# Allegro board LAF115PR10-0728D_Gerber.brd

Outline 228.4 x 155.5 mm; copper layers: TOP, GND1, IN1, VCC, IN2, IN3, GND2, BOTTOM. Coordinates in mm from the lower left corner of the outline.

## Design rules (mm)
net group 12: nets PCIE_RCOMPN PCIE_RCOMPP
net group CPU_DP3_AUX: nets CPU_DP3_AUXN CPU_DP3_AUXP
net group DDR-RESET: nets DDR4_DRAMRST# H_DRAMRST#
net group DIFFPAIR12: nets ICSP_CLK ICSP_DAT
net group DIFFPAIR15: nets NCT7718_DXN NCT7718_DXP
net group DIFFPAIR21: nets EDP_TX1 EDP_TX1#
net group DIFFPAIR22: nets USB_CAMERA_EDP USB_CAMERA_EDP#
net group DIFFPAIR24: nets USB3_CTX_DRX_N3 USB3_CTX_DRX_P3
net group DIFFPAIR25: nets USB3_CRX_DTX_N3 USB3_CRX_DTX_P3
net group DIFFPAIR27: nets PCIE_CTX_C_LANRX_N5 PCIE_CTX_C_LANRX_P5
net group GPU-XTAL_15/18_28/26: nets XTALIN XTALOUT
net group LAN_MDI2N: nets LAN_MDI2N LAN_MDI2P
net group LAN_MDI3N: nets LAN_MDI3N LAN_MDI3P
net group MDO2: nets MDO2+ MDO2-
net group MDO3: nets MDO3+ MDO3-
net group PECI: nets H_PECI PECI_EC
net group SW_USB_PN1: nets SW_USB_PN1 SW_USB_PP1
net group TYPEC_DP_N0: nets TYPEC_DP_N0 TYPEC_DP_P0
net group TYPEC_DP_N1: nets TYPEC_DP_N1 TYPEC_DP_P1
net group TYPEC_DP_N2: nets TYPEC_DP_N2 TYPEC_DP_P2
net group TYPEC_DP_N3: nets TYPEC_DP_N3 TYPEC_DP_P3
net group USB3_CRX_DTX_N3_C: nets USB3_CRX_DTX_N3_C USB3_CRX_DTX_P3_C
net group USB3_CTX_DRX_N3_C: nets USB3_CTX_DRX_N3_C USB3_CTX_DRX_P3_C
net group USB3_CTX_DRX_N3_R: nets USB3_CTX_DRX_N3_R USB3_CTX_DRX_P3_R
net group VGA_DP2_N0: nets VGA_DP2_N0 VGA_DP2_P0
net group VGA_DP2_N1: nets VGA_DP2_N1 VGA_DP2_P1
net group VGA_DP_AUXN: nets VGA_DP_AUXN VGA_DP_AUXP
net group 15: nets AUD_SPK_L+_C AUD_SPK_L-_C CLK_TP_SIO
net group AUDIO: nets AUD_HP1_JACK_L AUD_HP1_JACK_L1 AUD_HP1_JACK_R AUD_HP1_JACK_R1 CBN CBP CPVEE HPOUT_L HPOUT_R LINE1-L_C LINE1-L_R LINE1_L LINE1_R RING2 RING2_R SLEEVE SLEEVE_R
net group AUDIO-SPK: nets AUD_SPK_L+ AUD_SPK_L- AUD_SPK_R+ AUD_SPK_R+_C AUD_SPK_R- AUD_SPK_R-_C
net group CLK: nets CLK_PCIE_LAN_REQ# CLK_PCIE_NVME_REQ# CLK_PCIE_PEG_REQ# CLK_PCIE_WLAN_REQ# CLK_PCIE_WLAN_REQ#_R MEC_XTAL1 MEC_XTAL1_R MEC_XTAL2 PEG_CLKREQ# SUSCLK SUSCLK_EC SUSCLK_WLAN
net group CLK-24M: nets KBLR_XTAL_IN KBLR_XTAL_IN_R KBLR_XTAL_OUT KBLR_XTAL_OUT_R LANXIN LANXIN_R LANXOUT LANXOUT_R XCLK_BIASREF XTAL24_IN XTAL24_IN_R XTAL24_OUT
net group CPU: nets H_CATERR# H_PROCHOT# H_PROCHOT#_R H_THERMTRIP# H_VCCST_PWRGD VCCST_PWRGD XDP_OBS0_R XDP_OBS1_R XDP_OBS2_R XDP_OBS3_R
net group DDR-COMP: nets SM_RCOMP0 SM_RCOMP1 SM_RCOMP2
net group DIFFPAIR4: nets PCH_SMBDATA
net group DIFFPAIR23: nets DAT_TP_SIO
net group EDP: nets EDP_AUX EDP_AUX# EDP_AUX_DN EDP_AUX_DP EDP_TX0 EDP_TX0# EDP_TX0_DN EDP_TX0_DP EDP_TX1_DN EDP_TX1_DP
net group EDP-COMP: nets EDP_COMP
net group EMMC: nets EMMC_CLK EMMC_CLK_R EMMC_CMD EMMC_CMD_R EMMC_D0_R EMMC_D1_R EMMC_D2_R EMMC_D3_R EMMC_D4_R EMMC_D5_R EMMC_D6_R EMMC_D7_R EMMC_DATA0 EMMC_DATA1 EMMC_DATA2 EMMC_DATA3 EMMC_DATA4 EMMC_DATA5 EMMC_DATA6 EMMC_DATA7 EMMC_RCLK_R EMMC_RST# EMMC_RST#_R
net group ESPI: nets ESPI_CS# ESPI_RESET# PCH_ESPI_CLK PCH_ESPI_IO0 PCH_ESPI_IO1 PCH_ESPI_IO2 PCH_ESPI_IO3
net group HDA: nets DMIC_CLK DMIC_CLK_EDP DMIC_DATA DMIC_DATA_EDP HDA_BIT_CLK HDA_CODEC_BITCLK HDA_CODEC_RST# HDA_CODEC_SDIN0 HDA_CODEC_SDOUT HDA_CODEC_SYNC HDA_RST# HDA_SDIN0 HDA_SDOUT HDA_SYNC
net group HDMI: nets HDMI_CLK HDMI_CLK# HDMI_CLK#_R HDMI_CLK#_R_C HDMI_CLK_R HDMI_CLK_R_C HDMI_DATA0 HDMI_DATA0# HDMI_DATA0#_R HDMI_DATA0#_R_C HDMI_DATA0_R HDMI_DATA0_R_C HDMI_DATA1 HDMI_DATA1# HDMI_DATA1#_R HDMI_DATA1#_R_C HDMI_DATA1_R HDMI_DATA1_R_C HDMI_DATA2 HDMI_DATA2# HDMI_DATA2#_R HDMI_DATA2#_R_C HDMI_DATA2_R HDMI_DATA2_R_C
net group HDMI-DDC: nets CPU_DP1_CTRL_CLK CPU_DP1_CTRL_DATA DDC_CLK_HDMI DDC_DATA_HDMI
net group I2C: nets I2C0_SCL_TCH_PAD I2C0_SDA_TCH_PAD I2C_SCL_TP I2C_SDA_TP
net group KB: nets KSI0 KSI1 KSI2 KSI3 KSI4 KSI5 KSI6 KSI7 KSO0 KSO1 KSO2 KSO3 KSO4 KSO5 KSO6 KSO7 KSO8 KSO9 KSO10 KSO11 KSO12 KSO13 KSO14 KSO15
net group LAN: nets LAN_MDI0N LAN_MDI0P LAN_MDI1N LAN_MDI1P MDO0+ MDO0- MDO1+ MDO1-
net group PCIE: nets PCIE_CRX_C_LANTX_N5 PCIE_CRX_C_LANTX_P5 PCIE_CRX_LANTX_N5 PCIE_CRX_LANTX_P5 PCIE_CRX_WLANTX_N6 PCIE_CRX_WLANTX_P6 PCIE_CTX_C_WLANRX_N6 PCIE_CTX_C_WLANRX_P6 PCIE_CTX_LANRX_N5 PCIE_CTX_LANRX_P5 PCIE_CTX_WLANRX_N6 PCIE_CTX_WLANRX_P6
net group PCIE-GPU: nets PEG_GTX_C_HRX_N0 PEG_GTX_C_HRX_N1 PEG_GTX_C_HRX_N2 PEG_GTX_C_HRX_N3 PEG_GTX_C_HRX_P0 PEG_GTX_C_HRX_P1 PEG_GTX_C_HRX_P2 PEG_GTX_C_HRX_P3 PEG_GTX_HRX_N0 PEG_GTX_HRX_N1 PEG_GTX_HRX_N2 PEG_GTX_HRX_N3 PEG_GTX_HRX_P0 PEG_GTX_HRX_P1 PEG_GTX_HRX_P2 PEG_GTX_HRX_P3 PEG_HTX_C_GRX_N0 PEG_HTX_C_GRX_N1 PEG_HTX_C_GRX_N2 PEG_HTX_C_GRX_N3 PEG_HTX_C_GRX_P0 PEG_HTX_C_GRX_P1 PEG_HTX_C_GRX_P2 PEG_HTX_C_GRX_P3 PEG_HTX_GRX_N0 PEG_HTX_GRX_N1 PEG_HTX_GRX_N2 PEG_HTX_GRX_N3 PEG_HTX_GRX_P0 PEG_HTX_GRX_P1 PEG_HTX_GRX_P2 PEG_HTX_GRX_P3
net group PCIE-NVME: nets PCIE_CRX_NVMETX_N9 PCIE_CRX_NVMETX_N10 PCIE_CRX_NVMETX_N11 PCIE_CRX_NVMETX_N12 PCIE_CRX_NVMETX_P9 PCIE_CRX_NVMETX_P10 PCIE_CRX_NVMETX_P11 PCIE_CRX_NVMETX_P12 PCIE_CTX_C_NVMERX_N9 PCIE_CTX_C_NVMERX_N10 PCIE_CTX_C_NVMERX_N11 PCIE_CTX_C_NVMERX_N12 PCIE_CTX_C_NVMERX_P9 PCIE_CTX_C_NVMERX_P10 PCIE_CTX_C_NVMERX_P11 PCIE_CTX_C_NVMERX_P12 PCIE_CTX_NVMERX_N9 PCIE_CTX_NVMERX_N10 PCIE_CTX_NVMERX_N11 PCIE_CTX_NVMERX_N12 PCIE_CTX_NVMERX_P9 PCIE_CTX_NVMERX_P10 PCIE_CTX_NVMERX_P11 PCIE_CTX_NVMERX_P12
net group PLATFORM-CLK: nets CLK_ITPXDP_N CLK_ITPXDP_P CLK_PCIE_LAN_N2 CLK_PCIE_LAN_P2 CLK_PCIE_NVME_N4 CLK_PCIE_NVME_P4 CLK_PCIE_WLAN_N1 CLK_PCIE_WLAN_P1 CLK_PEG_VGA CLK_PEG_VGA#
net group RTC: nets PCH_RTCRST# PCH_RTCX1 PCH_RTCX2 SRTCRST#
net group SATA: nets SATA3_CRX_C_HDDTX_N0 SATA3_CRX_C_HDDTX_P0 SATA3_CRX_HDDTX_N0 SATA3_CRX_HDDTX_P0 SATA3_CTX_C_HDDRX_N0 SATA3_CTX_C_HDDRX_P0 SATA3_CTX_HDDRX_N0 SATA3_CTX_HDDRX_P0 SATA_CRX_C_ODDTX_N1 SATA_CRX_C_ODDTX_P1 SATA_CRX_ODDTX_N1 SATA_CRX_ODDTX_P1 SATA_CTX_C_ODDRX_N1 SATA_CTX_C_ODDRX_P1 SATA_CTX_ODDRX_N1 SATA_CTX_ODDRX_P1
net group SMBUS: nets CLK_SMB DAT_SMB MEM_SMBCLK MEM_SMBDATA MUX_I2C_CLK MUX_I2C_DATA PBAT_CHG_SMBCLK PBAT_CHG_SMBDAT PCH_SMBCLK SML0_SMBCLK SML0_SMBDATA SML1_SMBCLK SML1_SMBDATA THM_SML1_CLK THM_SML1_DATA TYPEC_SMBCLK TYPEC_SMBCLK_R TYPEC_SMBDA TYPEC_SMBDA_R VGA_SMB_CK3 VGA_SMB_DA3
net group SPI: nets PCH_SPI_CLK PCH_SPI_CLK_R PCH_SPI_CLK_TPM PCH_SPI_CS#0 PCH_SPI_CS#2 PCH_SPI_D0 PCH_SPI_D0_R PCH_SPI_D0_TPM PCH_SPI_D1 PCH_SPI_D1_R PCH_SPI_D1_TPM PCH_SPI_D2 PCH_SPI_D2_R PCH_SPI_D3 PCH_SPI_D3_R
net group SVID: nets H_CPU_SVIDALRT# VIDALERT_N VIDSCLK VIDSOUT
net group TYPEC-DP: nets CPU_DP2_AUXN CPU_DP2_AUXN_C CPU_DP2_AUXP CPU_DP2_AUXP_C CPU_DP2_N0 CPU_DP2_N0_C CPU_DP2_N1 CPU_DP2_N1_C CPU_DP2_N2 CPU_DP2_N2_C CPU_DP2_N3 CPU_DP2_N3_C CPU_DP2_P0 CPU_DP2_P0_C CPU_DP2_P1 CPU_DP2_P1_C CPU_DP2_P2 CPU_DP2_P2_C CPU_DP2_P3 CPU_DP2_P3_C DP_AUXN DP_AUXP DP_N0 DP_N1 DP_N2 DP_N3 DP_P0 DP_P1 DP_P2 DP_P3 TYPEC_DP_AUXN TYPEC_DP_AUXN_C TYPEC_DP_AUXP TYPEC_DP_AUXP_C TYPEC_DP_N0_C TYPEC_DP_N1_C TYPEC_DP_N2_C TYPEC_DP_N3_C TYPEC_DP_P0_C TYPEC_DP_P1_C TYPEC_DP_P2_C TYPEC_DP_P3_C TYPEC_RX2N TYPEC_RX2P TYPEC_TX2N TYPEC_TX2N_C TYPEC_TX2P TYPEC_TX2P_C
net group TYPEC-USB30: nets TYPEC_RX1N TYPEC_RX1P TYPEC_TX1N TYPEC_TX1N_C TYPEC_TX1P TYPEC_TX1P_C USB3_CRX_C_DTX_N4 USB3_CRX_C_DTX_P4 USB3_CRX_DTX_N4 USB3_CRX_DTX_P4 USB3_CTX_C_DRX_N4 USB3_CTX_C_DRX_P4 USB3_CTX_DRX_N4 USB3_CTX_DRX_P4
net group USB20: nets BOT_MUX_N BOT_MUX_N_R BOT_MUX_P BOT_MUX_P_R TOP_MUX_N TOP_MUX_N_R TOP_MUX_P TOP_MUX_P_R USB_PN1 USB_PN1_R USB_PN2 USB_PN2_R USB_PN3 USB_PN3_R USB_PN4 USB_PN4_R USB_PN5 USB_PN6 USB_PN6_R USB_PN7 USB_PN8 USB_PN8_TPNL USB_PN9 USB_PN10 USB_PP1 USB_PP1_R USB_PP2 USB_PP2_R USB_PP3 USB_PP3_R USB_PP4 USB_PP4_R USB_PP5 USB_PP6 USB_PP6_R USB_PP7 USB_PP8 USB_PP8_TPNL USB_PP9 USB_PP10
net group USB30: nets USB3_CRX_DTX_N1 USB3_CRX_DTX_N1_C USB3_CRX_DTX_N2 USB3_CRX_DTX_P1 USB3_CRX_DTX_P1_C USB3_CRX_DTX_P2 USB3_CTX_DRX_N1 USB3_CTX_DRX_N1_C USB3_CTX_DRX_N1_R USB3_CTX_DRX_N2 USB3_CTX_DRX_P1 USB3_CTX_DRX_P1_C USB3_CTX_DRX_P1_R USB3_CTX_DRX_P2
net group USB-COMP: nets USBCOMP
net group VRAM-ADD0: nets M0_MA0 M0_MA1 M0_MA2 M0_MA3 M0_MA4 M0_MA5 M0_MA6 M0_MA7 M0_MA8
net group VRAM-ADD1: nets M1_MA0 M1_MA1 M1_MA2 M1_MA3 M1_MA4 M1_MA5 M1_MA6 M1_MA7 M1_MA8
net group VRAM-CLK: nets M_CLK0 M_CLK1 M_CLK#0 M_CLK#1
net group VRAM-CTL0: nets M_CAS#0 M_CKE0 M_CS0B#0 M_RAS#0 M_WE#0
net group VRAM-CTL1: nets M_CAS#1 M_CKE1 M_CS1B#0 M_RAS#1 M_WE#1
net group VRAM-D0: nets M_DA0 M_DA1 M_DA2 M_DA3 M_DA4 M_DA5 M_DA6 M_DA7
net group VRAM-D1: nets M_DA8 M_DA9 M_DA10 M_DA11 M_DA12 M_DA13 M_DA14 M_DA15
net group VRAM-D2: nets M_DA16 M_DA17 M_DA18 M_DA19 M_DA20 M_DA21 M_DA22 M_DA23
net group VRAM-D3: nets M_DA24 M_DA25 M_DA26 M_DA27 M_DA28 M_DA29 M_DA30 M_DA31
net group VRAM-D4: nets M_DA32 M_DA33 M_DA34 M_DA35 M_DA36 M_DA37 M_DA38 M_DA39
net group VRAM-D5: nets M_DA40 M_DA41 M_DA42 M_DA43 M_DA44 M_DA45 M_DA46 M_DA47
net group VRAM-D6: nets M_DA48 M_DA49 M_DA50 M_DA51 M_DA52 M_DA53 M_DA54 M_DA55
net group VRAM-D7: nets M_DA56 M_DA57 M_DA58 M_DA59 M_DA60 M_DA61 M_DA62 M_DA63
net group VRAM-DBI: nets M_ADBI0 M_ADBI1 M_DBI0# M_DBI1# M_DBI2# M_DBI3# M_DBI4# M_DBI5# M_DBI6# M_DBI7#
net group VRAM-EDC: nets M_EDC_0 M_EDC_1 M_EDC_2 M_EDC_3 M_EDC_4 M_EDC_5 M_EDC_6 M_EDC_7
net group VRAM-WCK: nets M_WCKA0_0 M_WCKA0_0# M_WCKA0_1 M_WCKA0_1# M_WCKA1_0 M_WCKA1_0# M_WCKA1_1 M_WCKA1_1#
net group XDP: nets CFG0 CFG1 CFG2 CFG3 CFG4 CFG5 CFG6 CFG7 CFG8 CFG9 CFG10 CFG11 CFG12 CFG13 CFG14 CFG15 CFG16 CFG17 CFG18 CFG19 CPU_XDP_TCK0 PCH_JTAG_TCK1 PCH_RSMRST#_Q SOC_XDP_TDI SOC_XDP_TDO SOC_XDP_TMS SOC_XDP_TRST# XDP_HOOK0 XDP_ITP_PMODE XDP_PRDY# XDP_PREQ# XDP_PRSENT_CPU XDP_SPI_IO2 XDP_SPI_SI
nets with their own width: min track width 0.152; nets VCCSENSE VSSSENSE
nets with their own width: min track width 0.254; nets +1.0V_APLL +1.0V_VCCST +1.0V_VCCST_C +3.3V_ALW_DSW +3.3V_SPI +3VALW_PCH +3VLP +DP_VDDR +LAN_VDD33 +MPLL_PVDD +RTC_CELL +RTC_VCC +SPLL_PVDD +SPLL_VDDC +TPAN_VDD +TSVDD +VDD_CT +VDDR3 AC_B2B_S2_A AC_B2B_S2_B AC_B2B_S2_SW CFG_RCOMP HDMI_PLL_GND KB_BL_CTRL# KB_LED_DET_C LM393_P MCT0 MCT1 MCT2 MCT3 N17389450 N22328320 N22328488 N24193884 N24265247 N40598619
nets with their own width: min track width 0.305; nets +5V_KB_BL CPU_POPIRCOMP VDD10
nets with their own width: min track width 0.381; nets +1.8V_AVDD +1.8V_CPVDD +3V_DVDD +5V_AVDD +17.4V_BATT+ +FB0_VREFCL +FB0_VREFDL +FB1_VREFCL +FB1_VREFDL +MVREFDA +MVREFSA
nets with their own width: min track width 0.508; nets +1.0V_AMPHYPLL +1.0V_APLLEBB +1.0V_MPHYGT +1.0V_PRIM +1.0V_SRAM +1.0V_VCCSTG +1.0VS_VCCIO +1.2VP +1.8V_EMMC +1.8VALWP +1.35V_MEM_GFX +2.5VP +3.3V_ADP_DCIN +3.3V_CPS +3.3V_VBUS_IN +3.3V_VDD_PIC +3V_EMMC +3VALW +3VALW_EC +3VALWP +3VS +3VS_CAM +3VS_SSD +5V_CONN_P1 +5VS +DC_IN +DP_VDDC +RTC_CELL_VBAT +TP_VDD +VCC_CORE +VCC_GT +VCC_SA +VGA_CORE AUD_AGND BST_VCORE1 CCG4_CC1_P1 CCG4_CC2_P1 EC_AGND GND LOM_TCT LX_+1VALW PHASE_VCORE1 PWR_SELECT1
nets with their own width: min track width 0.762; nets +19VB_+1VALW LX2_CHG
nets with their own width: min track width 0.864; nets +5V_HDD
nets with their own width: min track width 1.016; nets +0.6V_DDR_VTT +2.5V_MEM VDDREG
nets with their own width: min track width 1.219; nets +BIF_VDDC
nets with their own width: min track width 1.321; nets +1.8V_PRIM
nets with their own width: min track width 1.524; nets +0.6VSP +5V_HDMI +5VS_ODD +DCBAT_LCD +PCIE_VDDC USB30_VCCC
nets with their own width: min track width 2.032; nets +3.3V_WLAN +5V_PVDD +5VALW +LCDVDD +LCDVDD_LCD USB20_VCCB USB30_VCCA
nets with their own width: min track width 3.048; nets +CCG_VBUS
nets with their own width: min track width 3.81; nets +19VB

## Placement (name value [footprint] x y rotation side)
C1  0.47U_0402_6.3V6K  [C_0402]  38.25 54.26 0 top
C2  0.1U_0402_16V7K  [C_0402]  212.64 57.42 180 top
C3  1U_0402_10V6K  [C_0402]  212.66 56.52 180 top
C4  0.1U_0603_50V7K  [C_0603]  206.15 57.57 180 bottom
C5  1000P_0402_50V7K  [C_0402]  207.1 57.42 90 bottom
C6  0.1U_0402_16V7K  [C_0402]  215.44 52.68 180 top
C7  0.1U_0402_16V7K  [C_0402]  215.44 51.79 180 top
C8  0.1U_0402_16V7K  [C_0402]  215.44 50.88 180 top
C9  0.1U_0402_16V7K  [C_0402]  215.44 49.99 180 top
C10  0.1U_0402_16V7K  [C_0402]  215.44 53.57 180 top
C11  0.1U_0402_16V7K  [C_0402]  215.44 54.46 180 top
C12  82P_0402_50V8J  [C_0402]  214.52 55.41 0 top
C14  33P_0402_50V8J  [C_0402]  212.57 45.09 270 top
C15  4.7U_0402_6.3V6M  [C_0402]  211.68 45.09 270 top
C16  10P_0402_50V8J  [C_0402]  212.63 41.43 90 top
C17  1U_0402_6.3V6K  [C_0402]  209.71 50.94 180 top
C18  .1U_0402_16V7K  [C_0402]  130.77 31.28 0 top
C19  0.1U_0402_16V7K  [C_0402]  127.05 26.65 270 top
C21  0.1U_0402_16V7K  [C_0402]  180.72 66.05 135 bottom
C22  470P_0603_50V8J  [C_0603]  86.84 118.55 90 bottom
C23  2200P_0402_50V7K  [C_0402]  182.26 61.25 225 bottom
C26  10P_0402_50V8J  [C_0402]  114.99 26.7 0 top
C27  10P_0402_50V8J  [C_0402]  117.26 25.2 90 top
C30  22U_0805_10V6M  [C_0805]  180.4 66.07 225 top
C31  1U_0402_10V6K  [C_0402]  205.48 36.81 270 top
C32  0.1U_0402_16V7K  [C_0402]  110.45 108.58 270 top
C33  100P_0402_50V8J  [C_0402]  124.65 43.29 180 top
C34  .1U_0402_16V7K  [C_0402]  49.53 41.56 90 top
C35  100P_0402_50V8J  [C_0402]  144.39 87.93 0 bottom
C36  100P_0402_50V8J  [C_0402]  140.66 88.05 180 bottom
C37  0.1U_0402_16V7K  [C_0402]  222.98 31.4 180 bottom
C39  68P_0201_50V8J  [C_0201]  215.32 56.99 270 top
C40  22U_0402_6.3V6M  [C_0402]  219.05 43.24 180 top
C41  22U_0402_6.3V6M  [C_0402]  219.05 44.45 180 top
C42  68P_0201_50V8J  [C_0201]  222.59 36.76 0 bottom
C43  68P_0201_50V8J  [C_0201]  215.53 60.41 90 top
C46  68P_0201_50V8J  [C_0201]  222.14 32.19 0 bottom
C47  68P_0201_50V8J  [C_0201]  205.8 58.64 180 bottom
C48  68P_0201_50V8J  [C_0201]  208.55 38.78 180 top
C49  68P_0201_50V8J  [C_0201]  214.41 45.91 270 top
C50  10P_0201_50V8J  [C_0201]  222.14 32.77 0 bottom
C51  68P_0201_50V8J  [C_0201]  95.54 35.92 0 bottom
C52  68P_0201_50V8J  [C_0201]  118.09 32.57 0 bottom
C53  68P_0201_50V8J  [C_0201]  40.48 60.35 90 top
C54  33P_0201_25V8J  [C_0201]  39.91 60.35 90 top
C55  68P_0201_50V8J  [C_0201]  42.44 56.14 0 top
C56  33P_0201_25V8J  [C_0201]  42.44 56.71 0 top
C57  0.1U_0402_25V6K  [C_0402]  40.31 97.16 270 top
C59  1U_0402_6.3V6K  [C_0402]  64.26 35.3 0 top
C60  22P_0402_50V8J  [C_0402]  66.81 31.02 180 top
C61  0.1U_0402_25V6  [C_0402]  66.68 29.19 90 top
C62  1U_0402_10V6K  [C_0402]  46.62 98.15 90 top
CA1  10U_0603_10V6M  [C_0603]  29.53 4.74 0 top
CA2  .1U_0402_16V7K  [C_0402]  29.25 7.03 180 top
CA3  10U_0603_10V6M  [C_0603]  29.53 5.95 0 top
CA4  .1U_0402_16V7K  [C_0402]  30.09 7.22 0 top
CA5  10U_0603_6.3V6M  [C_0603]  34.27 18.98 180 top
CA6  .1U_0402_16V7K  [C_0402]  32.93 17.92 0 top
CA7  .1U_0402_16V7K  [C_0402]  29.5 18.78 90 top
CA9  82P_0402_50V8J  [C_0402]  33.87 11.23 0 top
CA10  .1U_0402_16V7K  [C_0402]  21.98 15.81 90 top
CA11  10U_0603_10V6M  [C_0603]  20.53 16.94 90 top
CA12  10U_0603_6.3V6M  [C_0603]  19.75 7.98 0 top
CA13  10U_0603_6.3V6M  [C_0603]  24.32 6.26 180 top
CA14  .1U_0402_16V7K  [C_0402]  19.58 6.05 180 top
CA15  10U_0603_6.3V6M  [C_0603]  34.27 20.18 180 top
CA16  .1U_0402_16V7K  [C_0402]  31.36 16.77 0 top
CA17  .1U_0402_16V7K  [C_0402]  30.87 8.9 0 top
CA20  10U_0603_6.3V6M  [C_0603]  19.2 15.86 0 top
CA21  10U_0603_6.3V6M  [C_0603]  19.75 9.19 0 top
CA22  10U_0603_6.3V6M  [C_0603]  33.42 12.89 180 top
CA23  2.2U_0402_6.3V6M  [C_0402]  20.61 14.51 180 top
CA24  1U_0603_16V7  [C_0603]  22.22 11.34 270 top
CA25  1U_0603_16V7  [C_0603]  19.74 10.66 0 top
CA26  10U_0603_6.3V6M  [C_0603]  23.6 20.04 90 top
CA27  1000P_0402_50V7K  [C_0402]  27.04 5.95 0 top
CA28  1000P_0402_50V7K  [C_0402]  26.18 5.95 180 top
CA29  1000P_0402_50V7K  [C_0402]  25.02 2.98 270 top
CA30  1000P_0402_50V7K  [C_0402]  25.02 3.84 90 top
CA31  0.1U_0402_16V7K  [C_0402]  28.58 19.04 270 top
CA32  10U_0603_10V6M  [C_0603]  22.01 17.63 90 top
CA33  10U_0603_10V6M  [C_0603]  23.28 17.63 90 top
CA34  100P_0402_50V8J  [C_0402]  15.5 14.15 270 bottom
CA35  100P_0402_50V8J  [C_0402]  15.5 11.46 90 bottom
CA36  680P_0402_50V8J  [C_0402]  28.03 22.84 90 top
CA37  680P_0402_50V8J  [C_0402]  25.12 21.69 90 top
CA38  33P_0402_50V8J  [C_0402]  36.21 15.35 180 top
CA40  82P_0402_50V8J  [C_0402]  33.87 10.35 0 top
CA41  680P_0402_50V8J  [C_0402]  25.1 20.86 270 top
CA42  680P_0402_50V8J  [C_0402]  27.08 22.84 90 top
CA43  68P_0201_50V8J  [C_0201]  29.06 8.36 180 top
CA44  68P_0201_50V8J  [C_0201]  31.27 15.46 0 top
CA45  68P_0201_50V8J  [C_0201]  30.82 20.17 90 top
CA46  68P_0201_50V8J  [C_0201]  23.14 9.05 0 top
CA47  10P_0201_50V8J  [C_0201]  29.06 7.79 180 top
CA48  10P_0201_50V8J  [C_0201]  31.27 16.03 0 top
CA49  10P_0201_50V8J  [C_0201]  31.4 20.16 90 top
CA50  10P_0201_50V8J  [C_0201]  23.14 8.49 0 top
CC1  0.1U_0402_16V7K  [C_0402]  103.04 102.29 270 top
CC2  33P_0402_50V8J  [C_0402]  108.58 46.53 270 bottom
CC3  0.1U_0402_25V6  [C_0402]  129.19 39.4 270 bottom
CC4  1U_0402_6.3V6K  [C_0402]  103.82 35.08 270 bottom
CC5  1U_0402_6.3V6K  [C_0402]  101.52 44.28 0 top
CC6  15P_0201_25V8J  [C_0201]  142.88 75.02 90 bottom
CC7  15P_0201_25V8J  [C_0201]  142.88 72.38 270 bottom
CC8  6.8P_0402_50V8C  [C_0402]  106.05 50.23 90 top
CC9  6.8P_0402_50V8C  [C_0402]  103.4 50.24 180 top
CC10  1U_0402_6.3V6K  [C_0402]  100.63 29.32 180 bottom
CC11  0.1U_0402_10V7K  [C_0402]  101.77 31.97 270 bottom
CC12  0.1U_0402_16V7K  [C_0402]  142.94 93.5 90 bottom
CC13  0.1U_0402_16V7K  [C_0402]  143.82 94.02 0 bottom
CC14  1U_0402_6.3V6K  [C_0402]  148.29 91.04 180 bottom
CC15  100P_0402_50V8J  [C_0402]  139.74 92.92 0 bottom
CC17  12P_0201_25V8J  [C_0201]  144.35 43.54 180 bottom
CC18  12P_0201_25V8J  [C_0201]  143.26 46.05 180 bottom
CC26  10U_0402_6.3V6M  [C_0402]  106.04 76.41 90 top
CC27  10U_0402_6.3V6M  [C_0402]  104.89 67.55 270 top
CC28  10U_0402_6.3V6M  [C_0402]  105.13 63.6 0 top
CC29  10U_0402_6.3V6M  [C_0402]  116.57 83.32 270 top
CC30  10U_0402_6.3V6M  [C_0402]  105.91 82.79 270 top
CC31  10U_0402_6.3V6M  [C_0402]  106.04 89.46 270 top
CC32  1U_0402_6.3V6K  [C_0402]  105.27 69.23 0 top
CC33  1U_0402_6.3V6K  [C_0402]  117.97 70.46 90 top
CC34  1U_0402_6.3V6K  [C_0402]  117.96 73.54 90 top
CC35  1U_0402_6.3V6K  [C_0402]  104.97 82.8 270 top
CC36  22U_0603_6.3V6M  [C_0603]  105.78 73.19 90 top
CC37  22U_0603_6.3V6M  [C_0603]  105.72 85.44 90 top
CC38  22U_0603_6.3V6M  [C_0603]  104.21 70.65 270 top
CC39  10U_0402_6.3V6M  [C_0402]  106.04 91.68 270 top
CC40  1U_0402_6.3V6K  [C_0402]  118.17 64.35 0 top
CC41  1U_0402_6.3V6K  [C_0402]  130.67 62.4 90 top
CC42  1U_0402_6.3V6K  [C_0402]  144.45 62.08 0 top
CC43  1U_0402_6.3V6K  [C_0402]  120.46 78.32 0 top
CC44  1U_0402_6.3V6K  [C_0402]  103.94 104.04 270 top
CC45  1U_0402_6.3V6K  [C_0402]  158.91 39.73 90 top
CC46  1U_0402_6.3V6K  [C_0402]  161.44 39.75 0 top
CC47  1U_0402_6.3V6K  [C_0402]  161.47 37.82 0 top
CC48  1U_0402_6.3V6K  [C_0402]  161.47 38.84 0 top
CC49  10U_0402_6.3V6M  [C_0402]  119.72 67.07 180 top
CC50  10U_0402_6.3V6M  [C_0402]  120.73 73.23 270 top
CC51  1U_0402_6.3V6K  [C_0402]  120.14 66.2 270 top
CC52  1U_0402_6.3V6K  [C_0402]  158.02 39.73 90 top
CC53  1U_0402_6.3V6K  [C_0402]  157.13 39.73 90 top
CC54  1U_0402_6.3V6K  [C_0402]  156.24 39.73 90 top
CC55  1U_0402_6.3V6K  [C_0402]  126.23 62.38 90 top
CC56  1U_0402_6.3V6K  [C_0402]  119.19 47.02 90 top
CC57  1U_0402_6.3V6K  [C_0402]  123.08 60.86 90 top
CC58  1U_0402_6.3V6K  [C_0402]  128.26 50.44 90 top
CC59  47U_0805_6.3V6M  [C_0805]  133.8 49.78 180 top
CC60  1U_0402_6.3V6K  [C_0402]  129.75 58.64 90 top
CC61  0.5P_0402_50V8  [C_0402]  122.35 59.97 0 top
CC62  1U_0402_6.3V6K  [C_0402]  146.18 42.92 270 top
CC63  1U_0402_6.3V6K  [C_0402]  145.29 42.92 270 top
CC64  1U_0402_6.3V6K  [C_0402]  125.48 44.47 0 top
CC65  1P_0402_50V8  [C_0402]  125.47 43.56 0 top
CC66  1U_0402_6.3V6K  [C_0402]  122.28 56.99 180 top
CC67  1U_0402_6.3V6K  [C_0402]  122.38 59.08 0 top
CC68  1U_0402_6.3V6K  [C_0402]  124.31 56.49 0 top
CC69  0.1U_0201_6.3V6K  [C_0201]  109.09 53.33 270 bottom
CC70  0.1U_0201_6.3V6K  [C_0201]  109.42 57.19 180 bottom
CC71  1U_0201_6.3V6M  [C_0201]  101.86 42.45 90 top
CC72  1U_0402_6.3V6K  [C_0402]  125.34 62.38 90 top
CC73  0.1U_0402_10V7K  [C_0402]  130.8 54.8 270 top
CC74  47U_0805_6.3V6M  [C_0805]  130.68 48.85 90 top
CC75  1U_0402_6.3V6K  [C_0402]  129.92 56.89 270 top
CC76  47U_0603_6.3V6M  [C_0603]  144.54 52.66 270 top
CC77  47U_0603_6.3V6M  [C_0603]  144.5 78.48 90 top
CC78  0.1U_0402_10V7K  [C_0402]  125.48 45.42 0 top
CC79  1U_0402_6.3V6K  [C_0402]  130.11 39.4 270 bottom
CC80  22U_0603_6.3V6M  [C_0603]  104.19 56.82 90 top
CC81  22U_0603_6.3V6M  [C_0603]  102.92 56.82 90 top
CC82  0.5P_0402_50V8  [C_0402]  126.48 56.74 270 top
CC83  0.5P_0402_50V8  [C_0402]  124.84 60.22 90 top
CC84  47U_0603_6.3V6M  [C_0603]  128.2 61.82 90 top
CC85  1U_0402_6.3V6K  [C_0402]  102.95 40.48 180 top
CC86  1U_0402_6.3V6K  [C_0402]  123.57 49.69 180 top
CC87  1U_0402_6.3V6K  [C_0402]  129.24 62.44 90 top
CC88  82P_0402_50V8J  [C_0402]  104.41 54.91 180 top
CC90  100P_0402_50V8J  [C_0402]  106.36 103.09 90 top
CC91  47P_0402_50V8J  [C_0402]  110.28 60.39 0 bottom
CC94  33P_0402_50V8J  [C_0402]  104.74 35.08 270 bottom
CC95  33P_0402_50V8J  [C_0402]  126.48 54.01 90 top
CC96  33P_0402_50V8J  [C_0402]  144.77 40.68 0 top
CC97  2.2P_0402_50V8C  [C_0402]  95.95 49.81 90 top
CC98  2.2P_0402_50V8C  [C_0402]  32.06 13.95 0 top
CC99  2.2P_0402_50V8C  [C_0402]  96.84 49.81 90 top
CC100  0.5P_0402_50V8  [C_0402]  119.26 61.06 270 top
CC101  0.5P_0402_50V8  [C_0402]  144.4 42.92 270 top
CD1  10U_0603_6.3V6M~D  [C_0603]  81.91 43.28 90 top
CD2  10U_0603_6.3V6M~D  [C_0603]  78.83 43.27 90 top
CD3  1U_0402_6.3V6K~D  [C_0402]  80.83 43.59 90 top
CD4  1U_0402_6.3V6K~D  [C_0402]  79.91 43.58 90 top
CD5  1U_0402_6.3V6K~D  [C_0402]  75.75 44.22 90 top
CD6  10U_0603_6.3V6M~D  [C_0603]  74.54 43.73 90 top
CD7  10U_0603_6.3V6M~D  [C_0603]  73.33 43.73 90 top
CD8  10U_0603_6.3V6M~D  [C_0603]  72.06 43.73 90 top
CD9  0.1U_0402_16V7K~D  [C_0402]  76.83 43.86 90 top
CD10  2.2U_0402_6.3V6M  [C_0402]  69.04 69 180 top
CD11  1U_0402_6.3V6K~D  [C_0402]  77.38 55.79 180 top
CD12  1U_0402_6.3V6K~D  [C_0402]  79.19 64.87 180 top
CD13  1U_0402_6.3V6K~D  [C_0402]  79.56 47.98 180 top
CD14  1U_0402_6.3V6K~D  [C_0402]  70.82 52.73 0 top
CD15  1U_0402_6.3V6K~D  [C_0402]  78.57 63.69 180 top
CD16  1U_0402_6.3V6K~D  [C_0402]  79.13 73.76 180 top
CD17  1U_0402_6.3V6K~D  [C_0402]  80.31 92.43 0 top
CD18  1U_0402_6.3V6K~D  [C_0402]  79.48 102.14 180 top
CD19  10U_0603_6.3V6M~D  [C_0603]  70.46 78.15 0 top
CD20  10U_0603_6.3V6M~D  [C_0603]  79.4 81.63 180 top
CD21  10U_0603_6.3V6M~D  [C_0603]  79.43 79.8 180 top
CD22  10U_0603_6.3V6M~D  [C_0603]  79.43 78.4 180 top
CD23  10U_0603_6.3V6M~D  [C_0603]  79.4 76.55 180 top
CD24  10U_0603_6.3V6M~D  [C_0603]  79.14 75.09 180 top
CD25  10U_0603_6.3V6M~D  [C_0603]  79.4 66.9 180 top
CD26  10U_0603_6.3V6M~D  [C_0603]  70.03 107.36 0 top
CD27  330U_D2_2V_Y  [C_D2]  89.24 72.06 180 top
CD28  0.1U_0402_16V7K~D  [C_0402]  71.7 65.57 180 top
CD29  0.1U_0402_16V7K~D  [C_0402]  67.36 83.02 90 top
CD30  0.022U_0402_25V7K  [C_0402]  70.78 63.67 0 top
CD31  1U_0402_6.3V6K~D  [C_0402]  61.62 44.2 90 top
CD32  10U_0603_6.3V6M~D  [C_0603]  59.24 43.67 90 top
CD33  10U_0603_6.3V6M~D  [C_0603]  60.51 43.67 90 top
CD34  10U_0603_6.3V6M~D  [C_0603]  57.97 43.67 90 top
CD35  1U_0402_6.3V6K~D  [C_0402]  67.43 43.72 90 top
CD36  1U_0402_6.3V6K~D  [C_0402]  68.32 43.72 90 top
CD37  10U_0603_6.3V6M~D  [C_0603]  66.35 43.67 90 top
CD38  10U_0603_6.3V6M~D  [C_0603]  65.08 43.67 90 top
CD39  0.1U_0402_16V7K~D  [C_0402]  77.73 43.86 90 top
CD40  2.2U_0402_6.3V6M  [C_0402]  62.81 45.12 270 top
CD41  1U_0402_6.3V6K~D  [C_0402]  66.88 47.98 180 top
CD42  1U_0402_6.3V6K~D  [C_0402]  66.95 58.46 180 top
CD43  1U_0402_6.3V6K~D  [C_0402]  58.83 53.45 180 top
CD44  1U_0402_6.3V6K~D  [C_0402]  57.94 76.24 0 top
CD45  1U_0402_6.3V6K~D  [C_0402]  57.88 78.02 0 top
CD46  1U_0402_6.3V6K~D  [C_0402]  59.54 85.69 90 top
CD47  1U_0402_6.3V6K~D  [C_0402]  57.9 106.85 270 top
CD48  1U_0402_6.3V6K~D  [C_0402]  68.86 88.24 0 top
CD49  10U_0603_6.3V6M~D  [C_0603]  66.79 70.49 180 top
CD50  10U_0603_6.3V6M~D  [C_0603]  66.7 76.67 180 top
CD51  10U_0603_6.3V6M~D  [C_0603]  66.75 78.52 180 top
CD52  10U_0603_6.3V6M~D  [C_0603]  66.7 81.75 180 top
CD53  10U_0603_6.3V6M~D  [C_0603]  58.01 81.75 0 top
CD54  10U_0603_6.3V6M~D  [C_0603]  67.14 91.74 180 top
CD55  10U_0603_6.3V6M~D  [C_0603]  67.24 102.09 180 top
CD56  10U_0603_6.3V6M~D  [C_0603]  66.76 66.9 180 top
CD58  0.1U_0402_16V7K~D  [C_0402]  58.98 65.26 180 top
CD59  0.022U_0402_25V7K  [C_0402]  58.07 68.94 0 top
CE1  0.1U_0402_10V7K  [C_0402]  32.57 86.29 90 top
CE2  0.1U_0402_10V7K  [C_0402]  34.88 90.18 0 top
CE3  12P_0402_50V8J  [C_0402]  32.2 69.82 90 top
CE4  12P_0402_50V8J  [C_0402]  32.2 68.95 270 top
CE5  10U_0603_6.3V6M  [C_0603]  39.32 64.96 180 top
CE6  0.1U_0402_10V7K  [C_0402]  53.51 73.57 0 top
CE7  1000P_0402_50V7K  [C_0402]  32.86 78.85 90 top
CE8  1000P_0402_50V7K  [C_0402]  53.97 84.64 270 top
CE9  0.1U_0402_25V6  [C_0402]  53.01 83.72 90 top
CE10  0.1U_0402_25V6  [C_0402]  44.59 65.99 0 top
CE11  0.1U_0402_25V6  [C_0402]  45.6 64.76 270 top
CE12  0.1U_0402_25V6  [C_0402]  44.7 64.76 270 top
CE13  0.1U_0402_25V6  [C_0402]  33.46 74.73 270 top
CE14  0.1U_0402_10V7K  [C_0402]  32.08 71.92 180 top
CE15  0.1U_0402_25V6  [C_0402]  53.51 77.26 0 top
CE16  100P_0402_50V8J  [C_0402]  51.21 64.76 270 top
CE17  0.1U_0402_25V6  [C_0402]  34.75 85.77 180 top
CE19  0.047U_0402_16V4Z  [C_0402]  51.74 86.26 90 top
CE20  0.1U_0402_25V6  [C_0402]  42.24 87.16 180 top
CE21  0.1U_0402_25V6  [C_0402]  32.34 91.11 270 top
CE22  0.1U_0402_10V7K  [C_0402]  44.24 89.7 0 top
CE23  0.1U_0402_25V6  [C_0402]  47.63 64.76 270 top
CE24  1U_0603_16V7  [C_0603]  43.54 65.32 270 top
CE25  2200P_0402_25V7K  [C_0402]  31.19 78.13 270 top
CE26  47P_0402_50V8J  [C_0402]  40.86 90.1 270 top
CE28  220P_0402_50V8J  [C_0402]  53.52 71.8 0 top
CE30  2200P_0402_25V7K  [C_0402]  32.07 75.29 180 top
CE31  1000P_0402_50V7K  [C_0402]  49.9 86.26 90 top
CE32  100P_0402_50V8J  [C_0402]  35.67 66.25 180 top
CE33  2.2U_0402_6.3V6M  [C_0402]  33.14 66.11 270 top
CE34  100P_0402_50V8J  [C_0402]  46.74 63.85 90 top
CE35  33P_0402_50V8J  [C_0402]  53.98 80.56 0 top
CE36  68P_0201_50V8J  [C_0201]  42.33 86.34 180 top
CE37  10P_0201_50V8J  [C_0201]  33.62 79.11 90 top
CE38  68P_0201_50V8J  [C_0201]  54.87 76.47 270 top
CE39  10P_0201_50V8J  [C_0201]  54.29 76.47 270 top
CI1  0.1U_0402_10V7K  [C_0402]  19.83 94.66 180 top
CI2  0.1U_0402_10V7K  [C_0402]  19.83 93.7 180 top
CI3  0.1U_0402_10V7K  [C_0402]  19.83 96.69 180 top
CI4  0.1U_0402_10V7K  [C_0402]  19.83 95.74 180 top
CI5  0.1U_0402_10V7K  [C_0402]  19.83 92.62 180 top
CI6  0.1U_0402_10V7K  [C_0402]  19.83 91.67 180 top
CI7  0.1U_0402_10V7K  [C_0402]  19.83 90.72 180 top
CI8  0.1U_0402_10V7K  [C_0402]  19.83 89.77 180 top
CI9  .1U_0402_16V7K  [C_0402]  17.34 98.71 0 top
CL1  .1U_0402_16V7K  [C_0402]  26.66 85.79 90 top
CL2  .1U_0402_16V7K  [C_0402]  25.71 85.79 90 top
CL3  .1U_0402_16V7K  [C_0402]  28.81 81.5 0 top
CL4  .1U_0402_16V7K  [C_0402]  28.81 82.39 0 top
CL5  .1U_0402_16V7K  [C_0402]  21.54 81.97 0 bottom
CL6  .1U_0402_16V7K  [C_0402]  21.52 81.06 0 bottom
CL7  .1U_0402_16V7K  [C_0402]  21.99 80.13 0 bottom
CL8  .1U_0402_16V7K  [C_0402]  23.63 84.86 270 bottom
CL9  1U_0402_6.3V6K  [C_0402]  13.55 85.64 180 top
CL10  12P_0402_50V8J  [C_0402]  19.04 83.14 0 top
CL11  12P_0402_50V8J  [C_0402]  19.13 80.58 90 top
CL12  0.01U_0402_50V7K  [C_0402]  28.1 70.28 90 bottom
CL13  10P_1206_2KV8J  [C_1206]  18.94 76.37 0 bottom
CL15  .1U_0402_16V7K  [C_0402]  20.4 85.85 90 top
CL18  .1U_0402_16V7K  [C_0402]  24.76 78.84 90 bottom
CL19  .1U_0402_16V7K  [C_0402]  23.67 86.28 90 top
CL20  .1U_0402_16V7K  [C_0402]  28.86 80.45 270 top
CL22  1U_0402_10V6K  [C_0402]  22.77 86.28 90 top
CL23  .1U_0402_16V7K  [C_0402]  26.22 78.84 90 bottom
CL24  4.7U_0402_6.3V6M  [C_0402]  27.07 82.25 180 bottom
CL25  4.7U_0402_6.3V6M  [C_0402]  21.97 79.23 0 bottom
CM1  4.7U_0402_6.3V6M  [C_0402]  88.36 38.83 90 top
CM2  0.1U_0402_25V6  [C_0402]  87.41 38.83 90 top
CM3  4.7U_0402_6.3V6M  [C_0402]  93.33 30.27 180 top
CM4  0.1U_0402_25V6  [C_0402]  95.65 30.27 0 top
CM5  0.1U_0402_25V6  [C_0402]  86.46 38.83 90 top
CM6  100P_0402_50V8J  [C_0402]  83.85 39.74 270 top
CM7  0.1U_0402_16V7K  [C_0402]  76.3 31.13 270 top
CM8  22P_0402_50V8J  [C_0402]  75.41 30.22 90 top
CM9  68P_0201_50V8J  [C_0201]  89.11 39.01 90 top
CM10  68P_0201_50V8J  [C_0201]  80.78 39.24 90 top
CS1  0.01U_0402_50V7K  [C_0402]  189.84 32.57 90 top
CS2  0.01U_0402_50V7K  [C_0402]  188.95 32.57 90 top
CS3  0.01U_0402_50V7K  [C_0402]  187.93 32.57 90 top
CS4  0.01U_0402_50V7K  [C_0402]  187.04 32.57 90 top
CS5  1000P_0402_50V7K  [C_0402]  180.4 35.94 180 top
CS6  0.1U_0402_25V6K  [C_0402]  180.4 36.83 180 top
CS7  10U_0805_10V6K  [C_0805]  180.86 34.61 180 top
CS8  1U_0402_10V6K  [C_0402]  181.57 41.44 0 top
CS9  0.01U_0402_50V7K  [C_0402]  190.22 64.79 270 top
CS10  0.01U_0402_50V7K  [C_0402]  189.2 64.79 270 top
CS11  0.01U_0402_50V7K  [C_0402]  187.23 64.79 270 top
CS12  0.01U_0402_50V7K  [C_0402]  186.22 64.79 270 top
CS13  1000P_0402_50V7K  [C_0402]  200.31 61.52 270 top
CS14  0.1U_0402_25V6K  [C_0402]  199.42 61.52 270 top
CS15  10U_0805_10V6K  [C_0805]  198.27 61.04 180 top
CS16  0.22U_0402_16V7K  [C_0402]  36.62 36.95 270 bottom
CS17  0.22U_0402_16V7K  [C_0402]  35.73 36.95 270 bottom
CS18  0.22U_0402_16V7K  [C_0402]  34.08 36.95 270 bottom
CS19  0.22U_0402_16V7K  [C_0402]  33.19 36.95 270 bottom
CS20  0.22U_0402_16V7K  [C_0402]  31.03 36.95 270 bottom
CS21  0.22U_0402_16V7K  [C_0402]  30.14 36.95 270 bottom
CS22  0.22U_0402_16V7K  [C_0402]  27.98 36.95 270 bottom
CS23  0.22U_0402_16V7K  [C_0402]  27.09 36.95 270 bottom
CS24  10U_0805_25V6K~D  [C_0805]  27.28 26.42 0 top
CS25  1U_0402_6.3V6K~D  [C_0402]  28.22 28.7 0 top
CS26  0.1U_0402_25V6K~D  [C_0402]  28.22 27.74 0 top
CS27  1000P_0402_50V7K~D  [C_0402]  28.22 29.59 0 top
CS29  0.1U_0402_25V6K  [C_0402]  178.51 32.47 270 top
CS30  10U_0805_10V6K  [C_0805]  180.21 32.36 270 top
CS32  68P_0201_50V8J  [C_0201]  185.09 37.82 90 bottom
CS33  47U_0805_6.3V6M  [C_0805]  23.45 27.73 180 top
CS34  47U_0805_6.3V6M  [C_0805]  23.45 29.46 180 top
CS35  22U_0603_6.3V6M  [C_0603]  23.06 32.13 180 top
CS36  22U_0603_6.3V6M  [C_0603]  23.06 30.93 180 top
CT1  0.1U_0402_25V6  [C_0402]  37.07 118.49 180 bottom
CT2  1U_0603_16V7  [C_0603]  39.12 131.64 0 bottom
CT3  0.1U_0402_10V7K  [C_0402]  32.45 117.89 90 bottom
CT4  1U_0603_16V7  [C_0603]  31.94 126.53 180 bottom
CT5  0.1U_0402_10V7K  [C_0402]  30.29 123.68 0 bottom
CT6  0.1U_0402_10V7K  [C_0402]  31.88 125.15 270 top
CT7  0.1U_0402_10V7K  [C_0402]  37.77 130.5 180 bottom
CT8  1U_0603_16V7  [C_0603]  35.43 128.18 90 bottom
CT9  0.1U_0402_10V7K  [C_0402]  37.3 121.83 90 top
CT10  390P_0402_50V7K  [C_0402]  39.45 122.94 90 top
CT11  390P_0402_50V7K  [C_0402]  39.53 121.98 180 top
CT14  0.1U_0402_25V6  [C_0402]  31.56 117.29 0 top
CT15  1U_0603_25V  [C_0603]  30.23 118.09 90 bottom
CT17  2.2U_0603_10V6K  [C_0603]  30.09 122.54 180 top
CT19  10U_0402_6.3V6M  [C_0402]  17.15 117.78 270 bottom
CT20  0.1U_0402_10V7K  [C_0402]  23.57 117.69 0 bottom
CT21  0.1U_0402_10V7K  [C_0402]  21.92 127.05 270 top
CT22  0.1U_0402_10V7K  [C_0402]  23.57 118.58 0 bottom
CT23  0.1U_0402_10V7K  [C_0402]  16.26 117.78 270 bottom
CT24  0.1U_0402_10V7K  [C_0402]  23.71 127.4 0 bottom
CT25  0.1U_0402_10V7K  [C_0402]  23.7 126.5 0 bottom
CT26  0.1U_0402_10V7K  [C_0402]  24.18 124.75 0 bottom
CT27  0.1U_0402_10V7K  [C_0402]  24.18 123.86 0 bottom
CT28  0.1U_0402_10V7K  [C_0402]  23.85 122.18 0 bottom
CT29  0.1U_0402_10V7K  [C_0402]  23.83 121.29 0 bottom
CT30  0.1U_0402_10V7K  [C_0402]  23.83 120.39 0 bottom
CT31  0.1U_0402_10V7K  [C_0402]  23.82 119.5 0 bottom
CT32  0.1U_0402_10V7K  [C_0402]  19.3 116.34 90 bottom
CT33  0.1U_0402_10V7K  [C_0402]  18.41 116.34 90 bottom
CT34  0.1U_0402_10V7K  [C_0402]  21.72 127.75 90 bottom
CT35  0.1U_0402_10V7K  [C_0402]  20.83 127.75 90 bottom
CT36  0.1U_0402_10V7K  [C_0402]  19.56 128.65 270 bottom
CT37  0.1U_0402_10V7K  [C_0402]  18.67 128.65 270 bottom
CT38  0.1U_0402_10V7K  [C_0402]  25.75 129.93 180 bottom
CT39  10U_0603_25V6M  [C_0603]  11.37 120.69 0 bottom
CT40  0.1U_0402_10V7K  [C_0402]  11.95 123.99 180 top
CT41  0.1U_0402_10V7K  [C_0402]  11.95 123.1 180 top
CT42  0.1U_0402_10V7K  [C_0402]  12.4 117.33 180 bottom
CT43  0.1U_0402_10V7K  [C_0402]  12.4 116.44 180 bottom
CT44  0.47U_0402_50V6K  [C_0402]  10.66 119.68 0 top
CT45  0.47U_0402_50V6K  [C_0402]  11.06 120.76 0 top
CT46  0.47U_0402_50V6K  [C_0402]  10.35 120.49 90 bottom
CT47  0.47U_0402_50V6K  [C_0402]  10.35 119.63 270 bottom
CT50  2.2U_0402_6.3V6M  [C_0402]  17.91 125.66 270 top
CT53  1U_0603_25V6  [C_0603]  30.1 120.31 180 top
CT54  1U_0402_16V6K  [C_0402]  98.84 27.65 90 bottom
CT55  0.1U_0402_10V7K  [C_0402]  41.17 113.01 90 top
CT56  0.1U_0402_10V7K  [C_0402]  40.28 113.01 90 top
CT57  0.1U_0402_10V7K  [C_0402]  39.37 112.99 90 top
CT58  0.1U_0402_10V7K  [C_0402]  38.46 112.99 90 top
CT59  0.1U_0402_10V7K  [C_0402]  37.58 112.99 90 top
CT60  0.1U_0402_10V7K  [C_0402]  36.69 112.97 90 top
CT61  0.1U_0402_10V7K  [C_0402]  35.78 112.97 90 top
CT62  0.1U_0402_10V7K  [C_0402]  34.9 112.97 90 top
CT67  0.1U_0402_10V7K  [C_0402]  32.81 109.55 135 top
CT68  0.1U_0402_10V7K  [C_0402]  32.17 108.88 135 top
CT71  1U_0402_10V6K  [C_0402]  33.18 103.56 270 top
CT72  1U_0402_10V6K  [C_0402]  32.88 110.75 135 top
CT73  1U_0402_10V6K  [C_0402]  43.91 103.73 270 top
CT74  0.1U_0402_10V7K  [C_0402]  45.28 108.59 0 top
CT75  0.1U_0402_10V7K  [C_0402]  42.21 112.48 90 top
CT76  2.2U_0402_6.3V6M  [C_0402]  34.01 112.97 90 top
CT77  68P_0201_50V8J  [C_0201]  33.18 127.71 180 bottom
CT78  68P_0201_50V8J  [C_0201]  41.21 121.6 270 bottom
CT79  68P_0201_50V8J  [C_0201]  16.23 118.64 90 bottom
CT80  68P_0201_50V8J  [C_0201]  17.33 130.49 0 top
CT81  0.1U_0402_10V7K  [C_0402]  23.99 127.19 0 top
CT82  0.1U_0402_10V7K  [C_0402]  23.99 126.3 0 top
CT83  0.1U_0402_10V7K  [C_0402]  24.18 124.75 0 top
CT84  0.1U_0402_10V7K  [C_0402]  24.18 123.86 0 top
CT85  0.1U_0402_10V7K  [C_0402]  23.55 122.64 0 top
CT86  0.1U_0402_10V7K  [C_0402]  23.55 121.74 0 top
CT87  0.1U_0402_10V7K  [C_0402]  23.55 120.47 0 top
CT88  0.1U_0402_10V7K  [C_0402]  23.55 119.58 0 top
CT89  0.1U_0402_10V7K  [C_0402]  19.3 117.25 270 top
CT90  0.1U_0402_10V7K  [C_0402]  18.41 117.25 270 top
CT91  22U_0402_6.3V6M  [C_0402]  36.22 128.01 0 top
CT92  10U_0603_25V6M  [C_0603]  14.37 126.8 270 top
CT93  22U_0805_25V6M  [C_0805]  17.01 128.62 0 top
CU1  .1U_0402_16V7K  [C_0402]  25.03 59.16 180 top
CU2  .1U_0402_16V7K  [C_0402]  25.03 58.14 180 top
CU3  .1U_0402_16V7K  [C_0402]  17.67 37.39 270 top
CU4  .1U_0402_16V7K  [C_0402]  18.57 37.39 270 top
CU5  1U_0402_10V6K  [C_0402]  18.32 49.03 270 bottom
CU6  1U_0402_10V6K  [C_0402]  18.62 54.56 270 top
CU7  1U_0402_10V6K  [C_0402]  19.57 54.56 270 top
CU8  22U_0805_10V6M  [C_0805]  19.05 59.52 90 bottom
CU9  22U_0805_10V6M  [C_0805]  20.77 59.52 90 bottom
CU10  100U_1206_6.3V6M  [C_1206]  22.39 60.13 0 bottom
CU11  1U_0402_10V6K  [C_0402]  15.36 40.12 180 top
CU12  1U_0402_10V6K  [C_0402]  15.36 41.08 180 top
CU13  22U_0805_10V6M  [C_0805]  18.2 47.98 0 top
CU14  22U_0805_10V6M  [C_0805]  18.2 49.7 0 top
CU15  100U_1206_6.3V6M  [C_1206]  19.02 54.41 0 bottom
CU16  1U_0402_10V6K  [C_0402]  205.55 35 180 top
CU17  22U_0805_10V6M  [C_0805]  202.45 36.57 45 top
CU19  10P_0201_50V8J  [C_0201]  31.51 51.31 90 top
CU20  68P_0201_50V8J  [C_0201]  32.08 51.31 90 top
CU21  10P_0201_50V8J  [C_0201]  199.2 38.36 90 bottom
CU22  68P_0201_50V8J  [C_0201]  198.57 38.36 90 bottom
CU23  0.1U_0402_16V4Z  [C_0402]  32.2 45.08 270 top
CV1  0.22U_0402_16V7K  [C_0402]  111.16 148.33 270 bottom
CV2  0.22U_0402_16V7K  [C_0402]  112.06 148.33 270 bottom
CV3  0.22U_0402_16V7K  [C_0402]  112.97 148.31 270 bottom
CV4  0.22U_0402_16V7K  [C_0402]  113.87 148.31 270 bottom
CV5  0.22U_0402_16V7K  [C_0402]  117.1 142.09 208.7 top
CV6  0.22U_0402_16V7K  [C_0402]  116.67 142.88 208.7 top
CV7  0.22U_0402_16V7K  [C_0402]  118.01 143.64 299 top
CV8  0.22U_0402_16V7K  [C_0402]  118.79 144.07 299 top
CV11  0.082U_0402_16V  [C_0402]  114.78 133.91 90 top
CV15  0.68U_0402_10V  [C_0402]  114.33 137.77 180 top
CV17  10P_0402_50V8J  [C_0402]  109.7 146.83 180 bottom
CV18  10P_0402_50V8J  [C_0402]  109.68 143.5 270 bottom
CV19  10U_0603_6.3V6M  [C_0603]  111.19 133.55 90 top
CV20  1U_0402_6.3V4Z  [C_0402]  117.75 132.74 270 top
CV21  0.1U_0402_10V6K  [C_0402]  116.85 132.57 270 top
CV26  1U_0402_6.3V4Z  [C_0402]  115.59 130.95 90 top
CV27  10U_0603_6.3V6M  [C_0603]  112.9 130.56 180 top
CV28  0.68U_0402_10V  [C_0402]  116.67 136.16 180 top
CV29  0.68U_0402_10V  [C_0402]  117.48 135.17 270 top
CV30  10U_0603_6.3V6M  [C_0603]  115.45 129.47 270 top
CV33  1U_0402_6.3V4Z  [C_0402]  117.57 130.23 270 top
CV34  0.1U_0402_10V6K  [C_0402]  116.67 130.23 270 top
CV35  0.1U_0402_10V6K  [C_0402]  113.89 130.86 90 top
CV38  10U_0603_6.3V6M  [C_0603]  111.67 124.58 90 top
CV39  0.1U_0402_10V6K  [C_0402]  110.2 131.62 0 top
CV40  2.2U_0402_6.3V6M  [C_0402]  128.2 137.6 180 top
CV41  2.2U_0402_6.3V6M  [C_0402]  128.19 136.7 180 top
CV42  2.2U_0402_6.3V6M  [C_0402]  128.19 135.8 180 top
CV43  10U_0603_6.3V6M  [C_0603]  149.01 149.09 90 top
CV44  10U_0603_6.3V6M  [C_0603]  150.28 149.09 90 top
CV45  10U_0603_6.3V6M  [C_0603]  151.55 149.09 90 top
CV46  1U_0402_6.3V4Z  [C_0402]  113.08 140.47 0 top
CV47  2.2U_0402_6.3V6M  [C_0402]  127.12 131.85 180 top
CV48  2.2U_0402_6.3V6M  [C_0402]  126.46 130.86 270 top
CV49  0.1U_0402_10V6K  [C_0402]  146.66 149 90 top
CV50  0.1U_0402_10V6K  [C_0402]  138.15 146.85 90 top
CV51  0.1U_0402_10V6K  [C_0402]  137.27 146.85 90 top
CV52  0.1U_0402_10V6K  [C_0402]  136.38 146.85 90 top
CV53  0.1U_0402_10V6K  [C_0402]  130.11 126.9 90 top
CV54  10U_0603_6.3V6M  [C_0603]  116.17 115.36 270 bottom
CV55  10U_0603_6.3V6M  [C_0603]  114.96 115.36 270 bottom
CV56  1U_0402_6.3V4Z  [C_0402]  124.48 143.08 124.1 top
CV57  1U_0402_6.3V4Z  [C_0402]  125.15 140.83 180 top
CV58  1U_0402_6.3V4Z  [C_0402]  123.93 139.04 90 top
CV59  1U_0402_6.3V4Z  [C_0402]  123.04 139.04 90 top
CV60  1U_0402_6.3V4Z  [C_0402]  122.15 139.04 90 top
CV61  10U_0603_6.3V6M  [C_0603]  110.87 137.44 59.3 top
CV62  1U_0402_6.3V4Z  [C_0402]  120.26 136.88 90 top
CV63  0.1U_0402_10V6K  [C_0402]  119.27 136.79 90 top
CV64  1U_0402_6.3V4Z  [C_0402]  119 134 90 top
CV65  1U_0402_6.3V4Z  [C_0402]  119.9 134.72 90 top
CV66  1U_0402_6.3V4Z  [C_0402]  108.68 136.07 90 bottom
CV67  10U_0603_6.3V6M  [C_0603]  121.83 129.66 90 top
CV68  10U_0603_6.3V6M  [C_0603]  118.97 130.3 270 top
CV69  10U_0603_6.3V6M  [C_0603]  120.62 130.3 270 top
CV70  10U_0603_6.3V6M  [C_0603]  118.97 131.38 0 top
CV71  1U_0402_6.3V4Z  [C_0402]  121.57 132.7 0 top
CV72  1U_0402_6.3V4Z  [C_0402]  125.14 130.87 180 top
CV73  1U_0402_6.3V4Z  [C_0402]  120.71 133.01 90 top
CV74  1U_0402_6.3V4Z  [C_0402]  121.03 135.67 270 top
CV75  1U_0402_6.3V4Z  [C_0402]  122.51 135.53 0 top
CV76  1U_0402_6.3V4Z  [C_0402]  120.16 122.86 135 top
CV77  1U_0402_6.3V4Z  [C_0402]  127.89 133.14 180 top
CV78  1U_0402_6.3V4Z  [C_0402]  125.2 131.94 90 top
CV79  1U_0402_6.3V4Z  [C_0402]  115.52 123.25 315 top
CV80  1U_0402_6.3V4Z  [C_0402]  121.4 120.57 270 top
CV81  10U_0603_6.3V6M  [C_0603]  128.34 124.84 270 top
CV82  1U_0402_6.3V4Z  [C_0402]  127.71 126.37 180 top
CV84  10U_0603_6.3V6M  [C_0603]  132.06 120.19 180 top
CV85  1U_0402_6.3V4Z  [C_0402]  130.93 123.16 180 top
CV86  0.1U_0402_10V6K  [C_0402]  131.5 121.27 180 top
CV87  1U_0402_6.3V4Z  [C_0402]  125.14 129.97 180 top
CV88  10U_0603_6.3V6M  [C_0603]  122.08 128.52 0 top
CV89  1U_0402_6.3V4Z  [C_0402]  117.93 120.68 90 top
CV90  1U_0402_6.3V4Z  [C_0402]  117.03 120.68 90 top
CV91  10U_0603_6.3V6M  [C_0603]  133.07 120.52 0 top
CV92  1U_0402_6.3V4Z  [C_0402]  133.06 121.57 0 top
CV93  0.1U_0402_10V6K  [C_0402]  131.67 124.03 0 top
CV94  1U_0402_6.3V4Z  [C_0402]  129.71 146.43 180 bottom
CV95  1U_0402_6.3V4Z  [C_0402]  134.64 148.2 0 bottom
CV96  120P_0402_50V8J  [C_0402]  150.94 115.73 90 bottom
CV97  68P_0402_50V8J  [C_0402]  147.64 116.58 270 bottom
CV98  0.1U_0402_16V4Z  [C_0402]  129.71 120.88 90 top
CV99  0.1U_0402_16V4Z  [C_0402]  127.36 122.49 0 top
CV100  1U_0402_6.3V4Z  [C_0402]  116.88 124.63 315 top
CV101  1U_0402_6.3V4Z  [C_0402]  123.79 126.39 0 top
CV102  1U_0402_6.3V4Z  [C_0402]  123.4 127.29 0 top
CV103  1U_0402_6.3V4Z  [C_0402]  120.53 127.01 270 top
CV104  1U_0402_6.3V4Z  [C_0402]  116.17 123.91 315 top
CV105  1U_0402_6.3V4Z  [C_0402]  123.79 125.5 0 top
CV106  1U_0402_6.3V4Z  [C_0402]  114.84 122.58 315 top
CV107  1U_0402_6.3V4Z  [C_0402]  121.97 127.45 270 top
CV108  1U_0402_6.3V4Z  [C_0402]  115.86 126.37 135 top
CV109  1U_0402_6.3V4Z  [C_0402]  115.19 125.72 135 top
CV110  1U_0402_6.3V4Z  [C_0402]  114.56 125.06 135 top
CV111  1U_0402_6.3V4Z  [C_0402]  123.4 132.66 0 top
CV112  1U_0402_6.3V4Z  [C_0402]  122.49 133.61 180 top
CV113  1U_0402_6.3V4Z  [C_0402]  123.4 133.73 90 top
CV114  1U_0402_6.3V4Z  [C_0402]  126.1 133.73 270 top
CV115  1U_0402_6.3V4Z  [C_0402]  128.28 134.01 90 top
CV116  1U_0402_6.3V4Z  [C_0402]  126.1 134.81 90 top
CV117  1U_0402_6.3V4Z  [C_0402]  125.19 134.89 180 top
CV118  1U_0402_6.3V4Z  [C_0402]  125.16 135.78 180 top
CV119  1U_0402_6.3V4Z  [C_0402]  126.76 128.18 90 top
CV120  1U_0402_6.3V4Z  [C_0402]  125.15 141.72 180 top
CV121  1U_0402_6.3V4Z  [C_0402]  124.82 139.04 90 top
CV122  10U_0603_6.3V6M  [C_0603]  122.76 143.07 90 top
CV123  10U_0402_6.3V6M  [C_0402]  109.84 136.16 90 bottom
CV124  0.1U_0402_10V6K  [C_0402]  127.27 125.38 180 top
CV125  0.1U_0402_10V6K  [C_0402]  120.43 120.57 270 top
CV126  0.1U_0402_10V6K  [C_0402]  113.88 124.44 135 top
CV127  0.1U_0402_10V6K  [C_0402]  121.46 136.93 90 top
CV153  0.1U_0402_10V6K  [C_0402]  164.24 121.85 0 bottom
CV155  0.1U_0402_10V6K  [C_0402]  163.98 140.33 0 bottom
CV157  0.1U_0402_10V6K  [C_0402]  163.98 137.22 0 bottom
CV158  0.1U_0402_10V6K  [C_0402]  163.98 136.2 0 bottom
CV160  0.1U_0402_10V6K  [C_0402]  164.24 125.78 0 bottom
CV161  0.1U_0402_10V6K  [C_0402]  164.24 126.86 0 bottom
CV162  0.1U_0402_10V6K  [C_0402]  164.24 127.94 0 bottom
CV164  0.1U_0402_10V6K  [C_0402]  160.7 116.65 270 bottom
CV165  0.1U_0402_10V6K  [C_0402]  159.62 116.65 270 bottom
CV166  0.1U_0402_10V6K  [C_0402]  158.54 116.65 270 bottom
CV169  1U_0402_6.3V4Z  [C_0402]  161.61 116.64 270 top
CV170  1U_0402_6.3V4Z  [C_0402]  164.24 124.7 0 bottom
CV173  1U_0402_6.3V4Z  [C_0402]  164.24 130.1 0 bottom
CV174  0.01U_0402_16V7K  [C_0402]  128.61 127.09 90 top
CV175  0.01U_0402_16V7K  [C_0402]  128.61 129.06 180 top
CV176  0.01U_0402_16V7K  [C_0402]  128.43 130.32 90 top
CV177  0.01U_0402_16V7K  [C_0402]  127.36 130.86 270 top
CV178  0.01U_0402_16V7K  [C_0402]  147.55 149 90 top
CV179  0.01U_0402_16V7K  [C_0402]  110.2 132.51 0 top
CV180  1U_0402_6.3V4Z  [C_0402]  123.05 136.53 90 top
CV181  1U_0402_6.3V4Z  [C_0402]  126.04 137.06 180 top
CV198  0.1U_0402_10V6K  [C_0402]  157.43 149.06 90 top
CV210  0.1U_0402_10V6K  [C_0402]  160.3 149.08 90 top
CV211  0.1U_0402_10V6K  [C_0402]  159.34 149.06 90 top
CV213  0.1U_0402_10V6K  [C_0402]  158.38 149.06 90 top
CV216  0.1U_0402_10V6K  [C_0402]  164.24 120.77 0 bottom
CV219  0.1U_0402_10V6K  [C_0402]  157.61 116.64 270 bottom
CV221  0.1U_0402_10V6K  [C_0402]  151.93 116.65 270 bottom
CV225  10U_0603_6.3V6M  [C_0603]  163.77 119.87 0 top
CV227  1U_0402_6.3V4Z  [C_0402]  164.24 129.02 0 top
CV230  0.1U_0402_10V6K  [C_0402]  160.31 149.02 90 bottom
CV233  0.1U_0402_10V6K  [C_0402]  159.3 149.02 90 bottom
CV235  0.1U_0402_10V6K  [C_0402]  158.28 149.02 90 bottom
CV238  10U_0603_6.3V6M  [C_0603]  152.8 149.09 90 top
CV242  1U_0402_6.3V4Z  [C_0402]  163.98 136.2 0 top
CV243  1U_0402_6.3V4Z  [C_0402]  161.28 149.08 90 top
CV247  1U_0402_6.3V4Z  [C_0402]  162.24 149.08 90 top
CV248  1U_0402_6.3V4Z  [C_0402]  163.18 149.08 90 top
CV304  0.22U_0402_16V7K  [C_0402]  143.91 58.5 180 bottom
CV305  0.22U_0402_16V7K  [C_0402]  143.91 53.29 180 bottom
CV306  0.22U_0402_16V7K  [C_0402]  143.98 55.13 180 bottom
CV307  0.22U_0402_16V7K  [C_0402]  143.91 56.97 180 bottom
CV308  0.22U_0402_16V7K  [C_0402]  143.91 52.4 180 bottom
CV309  0.22U_0402_16V7K  [C_0402]  143.91 56.08 180 bottom
CV312  0.22U_0402_16V7K  [C_0402]  143.98 54.24 180 bottom
CV313  0.22U_0402_16V7K  [C_0402]  143.91 59.38 180 bottom
CV333  1U_0402_6.3V4Z  [C_0402]  160.63 116.65 270 top
CV334  1U_0402_6.3V4Z  [C_0402]  159.62 116.65 270 top
CV335  1U_0402_6.3V4Z  [C_0402]  158.54 116.65 270 top
CV336  1U_0402_6.3V4Z  [C_0402]  157.46 116.65 270 top
CV341  1U_0402_6.3V4Z  [C_0402]  163.98 137.21 0 top
CV342  1U_0402_6.3V4Z  [C_0402]  163.98 140.32 0 top
CV343  1U_0402_6.3V4Z  [C_0402]  164.05 147.25 0 top
CV344  1U_0402_6.3V4Z  [C_0402]  164.05 148.26 0 top
CV390  1U_0402_6.3V6K  [C_0402]  165.13 121.86 270 top
CV391  1U_0402_6.3V6K  [C_0402]  154.6 116.65 270 bottom
CV394  1U_0402_6.3V6K  [C_0402]  163.98 144.39 0 top
CV395  1U_0402_6.3V6K  [C_0402]  154.64 149.09 0 bottom
CW1  .1U_0402_16V7K  [C_0402]  76.84 116.22 90 bottom
CW2  .1U_0402_16V7K  [C_0402]  77.73 116.22 90 bottom
CW3  .1U_0402_16V7K  [C_0402]  68.71 116.7 270 top
CW4  .1U_0402_16V7K  [C_0402]  67.76 116.7 270 top
CW5  10U_0603_6.3V6M  [C_0603]  66.61 117.26 270 top
CW6  10U_0603_6.3V6M  [C_0603]  71.05 117.17 270 bottom
CW7  .1U_0402_16V7K  [C_0402]  70.9 136.47 270 top
CW8  .1U_0402_16V7K  [C_0402]  72.16 137.92 0 top
CW9  10P_0402_50V8J  [C_0402]  71.85 136.47 270 top
CX1  10U_0402_6.3V6M  [C_0402]  105.58 29.37 270 bottom
CX2  0.1U_0402_10V7K  [C_0402]  105.57 30.28 90 bottom
CX3  0.1U_0402_10V7K  [C_0402]  106.35 36.26 0 bottom
CX4  10U_0402_6.3V6M  [C_0402]  106.35 35.31 0 bottom
CX5  10U_0402_6.3V6M  [C_0402]  119.53 35.72 0 bottom
CX6  0.1U_0402_10V7K  [C_0402]  119.55 36.62 0 bottom
CX7  0.1U_0402_10V7K  [C_0402]  119.53 34.83 0 bottom
CZ1  0.1U_0402_10V7K  [C_0402]  162.57 29.96 270 top
CZ2  0.1U_0402_10V7K  [C_0402]  159.7 34.28 270 top
CZ3  470P_0402_50V7K  [C_0402]  163.18 34.34 270 top
CZ4  1U_0402_6.3V6K  [C_0402]  155.39 30.09 270 top
CZ5  0.1U_0402_10V7K  [C_0402]  156.4 30.09 270 top
CZ6  0.1U_0402_10V7K  [C_0402]  158.56 34.28 270 top
CZ7  0.1U_0402_10V7K  [C_0402]  157.42 30.09 270 top
CZ8  0.1U_0402_25V6  [C_0402]  121.03 66.23 270 top
CZ9  0.1U_0402_10V7K  [C_0402]  39.16 60.45 180 top
CZ10  470P_0402_50V7K  [C_0402]  44.08 58.36 270 top
CZ11  470P_0402_50V7K  [C_0402]  42.21 57.54 0 top
CZ12  0.1U_0402_10V7K  [C_0402]  40 55.88 180 top
CZ13  0.1U_0402_16V7K  [C_0402]  137.71 115.95 180 bottom
CZ14  100P_0402_50V8J  [C_0402]  133.8 114.48 180 bottom
CZ15  0.1U_0402_16V7K  [C_0402]  129.72 112.45 180 bottom
CZ16  0.1U_0402_16V7K  [C_0402]  129.48 107.67 180 bottom
CZ17  1U_0402_6.3V6K  [C_0402]  126.74 108.89 180 bottom
CZ18  330P_0402_50V7K  [C_0402]  122.66 111.52 0 bottom
CZ19  330P_0402_50V7K  [C_0402]  122.67 110.62 0 bottom
CZ20  0.1U_0402_10V7K  [C_0402]  122.62 107.22 90 bottom
CZ21  1U_0402_6.3V6K  [C_0402]  127.32 50.45 90 top
CZ22  0.1U_0402_10V7K  [C_0402]  163.18 31.55 90 top
CZ23  1U_0402_6.3V6K  [C_0402]  35.21 59.38 270 top
CZ25  1U_0402_6.3V6K  [C_0402]  37.31 55.88 0 top
CZ26  1U_0402_6.3V6K  [C_0402]  136.86 117.01 90 bottom
CZ27  0.1U_0402_10V7K  [C_0402]  135.87 114.24 180 bottom
CZ28  0.1U_0402_10V7K  [C_0402]  133.34 117.93 0 bottom
CZ29  1U_0402_6.3V6K  [C_0402]  126.46 113.53 180 bottom
CZ30  0.1U_0402_10V7K  [C_0402]  128.81 110.56 0 bottom
CZ31  0.1U_0402_10V7K  [C_0402]  124.29 114.36 90 bottom
CZ32  0.1U_0402_10V7K  [C_0402]  83.47 117.41 180 top
CZ33  1000P_0402_25V8J  [C_0402]  85.56 113.38 180 top
CZ36  1U_0402_6.3V6K  [C_0402]  86.37 111.49 0 top
CZ37  1U_0402_6.3V6K  [C_0402]  80.88 116.19 90 top
CZ40  0.1U_0402_10V7K  [C_0402]  80.43 111.58 0 top
CZ46  0.1U_0402_16V7K  [C_0402]  78.42 113.61 0 top
D1  -  [BAS40C_SOT23-3]  40.09 51.99 180 top
D3  -  [BAT54C-7-F_SOT23-3]  176.57 72.71 45 top
D4  -  [BAT54C-7-F_SOT23-3]  166.34 30.17 180 top
D5  -  [RB551V-30_SOD323-2]  215.43 40.36 90 top
D6  -  [RB551V-30_SOD323-2]  109.17 26.63 0 bottom
D7  RB751S40T1G_SOD523-2  [RB520SM-30T2R_EMD2-2]  67.93 29.83 90 top
DA1  -  [L03ESDL5V0CC3-2_SOT23-3]  18.51 3.28 90 top
DA2  -  [L03ESDL5V0CC3-2_SOT23-3]  23.12 3.26 90 top
DA3  -  [BAT54C-7-F_SOT23-3]  35.57 12.7 270 top
DA4  -  [L03ESDL5V0CC3-2_SOT23-3]  21.97 25.59 180 top
DA5  AZ5123-02S.R7G_SOT23-3  [AZ5123-02SPR7G_SOT23-3]  17.27 7.08 0 top
DA6  -  [AZC199-02SPR7G_SOT23-3]  210.12 40.3 270 bottom
DA7  -  [L03ESDL5V0CC3-2_SOT23-3]  18.1 23.31 180 top
DC2  RB751S40T1G_SOD523-2  [RB520SM-30T2R_EMD2-2]  77.16 112.2 0 top
DE1  AZ5125-01H.R7G_SOD523-2  [AZ5125-01HPR7G_SOD523-2]  33.91 88.29 270 top
DE2  -  [RB551V-30_SOD323-2]  29.69 89.26 90 top
DI1  -  [BAW56W_SOT323-3]  24.33 111.36 0 top
DT1  -  [RB551V-30_SOD323-2]  30.59 125.97 270 top
DT2  -  [RB551V-30_SOD323-2]  33.24 124.88 270 top
DT3  AZ5B75-01B.R7G_CSP0603P2Y2  [ESD101-B1-02ELS_TSSLP-2-4-2]  10.24 123.87 90 top
DT4  AZ5B75-01B.R7G_CSP0603P2Y2  [ESD101-B1-02ELS_TSSLP-2-4-2]  10.24 123.25 270 top
DT5  AZ5B75-01B.R7G_CSP0603P2Y2  [ESD101-B1-02ELS_TSSLP-2-4-2]  11.54 118.46 90 top
DT6  AZ5B75-01B.R7G_CSP0603P2Y2  [ESD101-B1-02ELS_TSSLP-2-4-2]  11.54 117.84 270 top
DT7  AZ5B75-01B.R7G_CSP0603P2Y2  [ESD101-B1-02ELS_TSSLP-2-4-2]  10.24 123.87 90 bottom
DT8  AZ5B75-01B.R7G_CSP0603P2Y2  [ESD101-B1-02ELS_TSSLP-2-4-2]  10.24 123.25 270 bottom
DT9  AZ5B75-01B.R7G_CSP0603P2Y2  [ESD101-B1-02ELS_TSSLP-2-4-2]  10.58 117.27 90 bottom
DT10  AZ5B75-01B.R7G_CSP0603P2Y2  [ESD101-B1-02ELS_TSSLP-2-4-2]  10.58 116.64 270 bottom
DW1  RB751S40T1G_SOD523-2  [RB520SM-30T2R_EMD2-2]  46 101.01 90 top
DW2  RB751S40T1G_SOD523-2  [RB520SM-30T2R_EMD2-2]  40.86 98.62 90 top
DZ1  -  [RB751S40T1G_SOD523-2]  96.44 44.88 90 top
DZ2  -  [RB751S40T1G_SOD523-2]  158.56 29.69 90 top
DZ3  -  [RB751S40T1G_SOD523-2]  108.46 47.79 0 bottom
DZ4  -  [RB751S40T1G_SOD523-2]  147.58 88.81 90 bottom
DZ5  -  [RB751S40T1G_SOD523-2]  160.69 28.88 90 top
EC2301  0.1U_0402_25V6  [C_0402]  17.26 8.21 270 bottom
EC2302  0.1U_0402_25V6  [C_0402]  26.16 23.96 90 top
